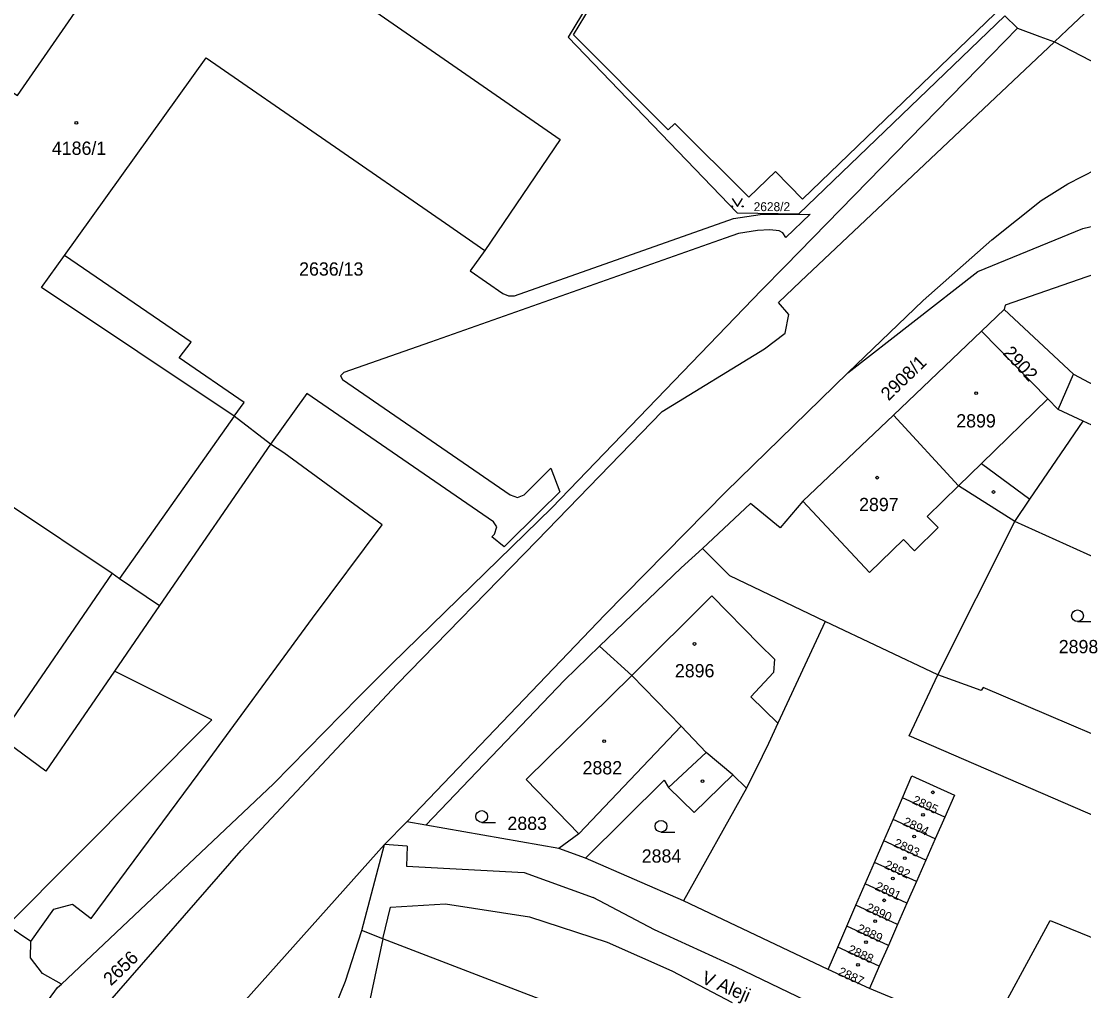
# Model space of a CAD drawing. Extents: x -527335 to -526256, y -1079142 to -1077836.
# Drawn here: x -527027.3 to -526891.4, y -1078723.7 to -1078599.7 of the extents above; entities that cross this region are included whole.
import ezdxf

# ---------------------------------------------------------------- set-up
doc = ezdxf.new("R2010")
doc.units = 0
for name, color, linetype in [('Hranice parcel', 7, 'Continuous'), ('Parcelní čísla', 7, 'Continuous'), ('Pop  PČ popisy', 7, 'Continuous'), ('Vnitřní kresba', 7, 'Continuous'), ('Značky budov', 7, 'Continuous'), ('Značky kultur', 7, 'Continuous')]:
    doc.layers.add(name, color=color, linetype=linetype)

msp = doc.modelspace()

# ---------------------------------------------------------------- linework, layer by layer
at = {"layer": 'Hranice parcel'}
for p, q in [((-526895.17, -1078602.34), (-526879.54, -1078610.46)), ((-526901.58, -1078636.57), (-526904.48, -1078639.35)), ((-526892.72, -1078644.86), (-526901.58, -1078636.57)), ((-526904.48, -1078639.35), (-526915.77, -1078650.08)), ((-526894.69, -1078649.36), (-526892.72, -1078644.86)), ((-527000.1, -1078650.22), (-527014.76, -1078670.99)), ((-526891.48, -1078650.84), (-526894.69, -1078649.36)), ((-526910.1, -1078683.31), (-526900.22, -1078663.69)), ((-526884.81, -1078670.65), (-526900.22, -1078663.69)), ((-526910.1, -1078683.31), (-526924.49, -1078676.46)), ((-526949.23, -1078683.38), (-526953.38, -1078679.65)), ((-526934.57, -1078697.78), (-526936.31, -1078696.09)), ((-526934.57, -1078697.78), (-526942.6, -1078712.19)), ((-526915.81, -1078701.79), (-526914.61, -1078699.02)), ((-526909.18, -1078701.49), (-526914.61, -1078699.02)), ((-526916.99, -1078704.52), (-526915.81, -1078701.79)), ((-526910.4, -1078704.26), (-526915.81, -1078701.79)), ((-526909.18, -1078701.49), (-526910.4, -1078704.26)), ((-526978.03, -1078702.08), (-526980.85, -1078705.02)), ((-526975.57, -1078702.51), (-526978.03, -1078702.08)), ((-526958.56, -1078705.51), (-526975.57, -1078702.51)), ((-526918.19, -1078707.29), (-526916.99, -1078704.52)), ((-526911.6, -1078706.99), (-526916.99, -1078704.52)), ((-526910.4, -1078704.26), (-526911.6, -1078706.99)), ((-526980.85, -1078705.02), (-526998.63, -1078724.92)), ((-526955.16, -1078706.76), (-526958.56, -1078705.51)), ((-526942.6, -1078712.19), (-526955.16, -1078706.76)), ((-526919.38, -1078710.05), (-526918.19, -1078707.29)), ((-526912.82, -1078709.75), (-526918.19, -1078707.29)), ((-526911.6, -1078706.99), (-526912.82, -1078709.75)), ((-526920.56, -1078712.77), (-526919.38, -1078710.05)), ((-526914.03, -1078712.51), (-526919.38, -1078710.05)), ((-526912.82, -1078709.75), (-526914.03, -1078712.51)), ((-526924.11, -1078720.97), (-526942.6, -1078712.19)), ((-526921.72, -1078715.45), (-526920.56, -1078712.77)), ((-526915.22, -1078715.23), (-526920.56, -1078712.77)), ((-526914.03, -1078712.51), (-526915.22, -1078715.23)), ((-526922.88, -1078718.12), (-526921.72, -1078715.45)), ((-526916.4, -1078717.9), (-526921.72, -1078715.45)), ((-526915.22, -1078715.23), (-526916.4, -1078717.9)), ((-526924.11, -1078720.97), (-526922.88, -1078718.12)), ((-526917.58, -1078720.58), (-526922.88, -1078718.12)), ((-526916.4, -1078717.9), (-526917.58, -1078720.58)), ((-526918.83, -1078723.42), (-526924.11, -1078720.97)), ((-526917.58, -1078720.58), (-526918.83, -1078723.42))]:
    msp.add_line(p, q, dxfattribs=at)
for points in [[(-527032.9, -1078614.69), (-527028.96, -1078608.95), (-527028.74, -1078608.62), (-527027.84, -1078609.21), (-527013.93, -1078589.06), (-527018.97, -1078585.47), (-527022.71, -1078582.8), (-527034.32, -1078599.25), (-527035, -1078600.21), (-527045.31, -1078592.89), (-527044.64, -1078591.95), (-527045.34, -1078591.68), (-527030.72, -1078570.54), (-527019.5, -1078578.37), (-527020.66, -1078580.03), (-527011.71, -1078586.28), (-527007.77, -1078580.59), (-526958.39, -1078614.81), (-526968.02, -1078629.02)], [(-526886.71, -1078584.76), (-526887.47, -1078583.94), (-526927.4, -1078622.44), (-526930.86, -1078618.91), (-526934.27, -1078622.19), (-526943.73, -1078612.76), (-526944.56, -1078613.6), (-526956.67, -1078601.43), (-526954.52, -1078597.86), (-526954.82, -1078597.51)], [(-526895.17, -1078602.34), (-526893.54, -1078600.8), (-526885.48, -1078593.16)], [(-526954.82, -1078597.51), (-526957.37, -1078601.73), (-526935.75, -1078624.2), (-526927.86, -1078624.35), (-526901.5, -1078599), (-526901.11, -1078599.39)], [(-526901.11, -1078599.39), (-526900.32, -1078600.17), (-526899.88, -1078600.6)], [(-527022.2, -1078722.85), (-526995.09, -1078697.22), (-526984.19, -1078686.17), (-526979.99, -1078681.95), (-526959.44, -1078661.92), (-526932.63, -1078634.11), (-526929.59, -1078631.02), (-526904.86, -1078605.7), (-526899.88, -1078600.6)], [(-526899.88, -1078600.6), (-526897.02, -1078601.66), (-526895.17, -1078602.34)], [(-527072.22, -1078805.43), (-527063.35, -1078791.03), (-527051.39, -1078772.86), (-527021.8, -1078732.24), (-527016.31, -1078725.38), (-526999.22, -1078705.77), (-526979.26, -1078684.5), (-526961.36, -1078666.17), (-526945.34, -1078649.61), (-526932.24, -1078641.62), (-526929.63, -1078639.61), (-526929.14, -1078637.23), (-526930.46, -1078635.68), (-526927.65, -1078633), (-526895.17, -1078602.34)], [(-527000.1, -1078650.22), (-527024.76, -1078633.76), (-527021.82, -1078629.67), (-527003.67, -1078604.4), (-526973.08, -1078625.53), (-526968.02, -1078629.02)], [(-526921.59, -1078644.68), (-526911.97, -1078635.42), (-526903.16, -1078627.64), (-526896.85, -1078622.64), (-526893.43, -1078620.48), (-526889.76, -1078618.63), (-526885.07, -1078616.68), (-526879.09, -1078614.67), (-526871.32, -1078612.59), (-526869.37, -1078612.14)], [(-526921.59, -1078644.68), (-526904.95, -1078631.71), (-526891.51, -1078626.22), (-526880.24, -1078623.51), (-526871.73, -1078622.35), (-526857.21, -1078622.49), (-526853.17, -1078623.18)], [(-526968.02, -1078629.02), (-526969.91, -1078631.61), (-526965.71, -1078634.53), (-526965, -1078634.84), (-526964.22, -1078634.81), (-526936.22, -1078624.93), (-526932.79, -1078624.4), (-526926.41, -1078624.36), (-526929.51, -1078627.35), (-526929.91, -1078626.76), (-526930.39, -1078626.49), (-526931.57, -1078626.38), (-526933.16, -1078626.45), (-526935.56, -1078626.83), (-526937.3, -1078627.43), (-526974.99, -1078640.74), (-526986.08, -1078644.63), (-526986.49, -1078645.05), (-526986.23, -1078645.53), (-526964.78, -1078660.29), (-526963.85, -1078660.61), (-526963.02, -1078660.27), (-526959.57, -1078656.88), (-526958.42, -1078659.89), (-526960.97, -1078662.37), (-526965.58, -1078666.91), (-526967.12, -1078665.64), (-526966.8, -1078665.3), (-526966.51, -1078664.38), (-526966.91, -1078663.73), (-526990.82, -1078647.32), (-526995.44, -1078653.79), (-527000.1, -1078650.22)], [(-526878.81, -1078628.66), (-526882.67, -1078629.51), (-526901.46, -1078636.01), (-526901.58, -1078636.57)], [(-526894.69, -1078649.36), (-526896.02, -1078648), (-526904.48, -1078639.35)], [(-526978.03, -1078702.08), (-526952.67, -1078675.63), (-526937.2, -1078659.88), (-526921.59, -1078644.68)], [(-526892.72, -1078644.86), (-526888.78, -1078646.91), (-526881.81, -1078650.35)], [(-526915.77, -1078650.08), (-526927.35, -1078661.1), (-526930.24, -1078664.51), (-526934.06, -1078661.4), (-526940.18, -1078667.13)], [(-526900.22, -1078663.69), (-526907.42, -1078659.13), (-526915.77, -1078650.08)], [(-526900.22, -1078663.69), (-526898.33, -1078660.82), (-526891.48, -1078650.84)], [(-526884.81, -1078670.65), (-526875.97, -1078658.01), (-526891.48, -1078650.84)], [(-527028.7, -1078661.6), (-527015.73, -1078670.3), (-527014.76, -1078670.99)], [(-526940.18, -1078667.13), (-526942.9, -1078669.62), (-526953.38, -1078679.65)], [(-526924.49, -1078676.46), (-526936.71, -1078670.65), (-526940.18, -1078667.13)], [(-527014.76, -1078670.99), (-527009.64, -1078674.44), (-527015.39, -1078682.81)], [(-526924.49, -1078676.46), (-526930.54, -1078689.49), (-526931.74, -1078692.06), (-526932.57, -1078693.74), (-526934.57, -1078697.78)], [(-526953.38, -1078679.65), (-526957.82, -1078683.96), (-526975.57, -1078702.51)], [(-527015.39, -1078682.81), (-527024.2, -1078695.62), (-527030.14, -1078691.25), (-527037.08, -1078701.34), (-527042.08, -1078697.91)], [(-527022.2, -1078722.85), (-527024.62, -1078721.48), (-527026.17, -1078719.51), (-527026.1, -1078717.42), (-527029.13, -1078715.35), (-527002.95, -1078689.07), (-527015.39, -1078682.81)], [(-526949.23, -1078683.38), (-526962.73, -1078696.68), (-526956.02, -1078703.63), (-526958.56, -1078705.51)], [(-526936.31, -1078696.09), (-526939.72, -1078693.23), (-526942.93, -1078689.86), (-526949.23, -1078683.38)], [(-526887.47, -1078692.06), (-526904.29, -1078684.93), (-526904.54, -1078685.32), (-526910.1, -1078683.31)], [(-526955.16, -1078706.76), (-526945.11, -1078696.79), (-526944.54, -1078697.69), (-526941.25, -1078700.91), (-526936.31, -1078696.09)], [(-526914.61, -1078699.02), (-526913.4, -1078696.22), (-526907.94, -1078698.67), (-526909.18, -1078701.49)], [(-526943.47, -1078731.53), (-526981.07, -1078717.06), (-526983.77, -1078716), (-526980.85, -1078705.02)], [(-526903.84, -1078729.73), (-526895.72, -1078714.74), (-526874.21, -1078723.48)], [(-527026.84, -1078728.96), (-527025.8, -1078727.55), (-527022.69, -1078723.31), (-527022.2, -1078722.85)], [(-526903.84, -1078729.73), (-526908.52, -1078727.66), (-526909.18, -1078727.41), (-526918.83, -1078723.42)]]:
    msp.add_lwpolyline(points, dxfattribs=at)
at = {"layer": 'Vnitřní kresba'}
for p, q in [((-527005.61, -1078640.76), (-527021.82, -1078629.67)), ((-527007.15, -1078642.76), (-527005.61, -1078640.76)), ((-526998.84, -1078648.48), (-527007.15, -1078642.76)), ((-527000.1, -1078650.22), (-526998.84, -1078648.48)), ((-526904.5, -1078656.28), (-526896.02, -1078648)), ((-526995.44, -1078653.79), (-527009.64, -1078674.44)), ((-526993.74, -1078654.92), (-526995.44, -1078653.79)), ((-526981.15, -1078664.11), (-526993.74, -1078654.92)), ((-526907.42, -1078659.13), (-526904.5, -1078656.28)), ((-526904.5, -1078656.28), (-526898.33, -1078660.82)), ((-526911.43, -1078663.04), (-526907.42, -1078659.13)), ((-526927.35, -1078661.1), (-526918.8, -1078670.23)), ((-526910.03, -1078664.47), (-526911.43, -1078663.04)), ((-526990.1, -1078676.05), (-526981.15, -1078664.11)), ((-526913.07, -1078667.44), (-526910.03, -1078664.47)), ((-526918.8, -1078670.23), (-526914.47, -1078666)), ((-526914.47, -1078666), (-526913.07, -1078667.44)), ((-527015.73, -1078670.3), (-527030.14, -1078691.25)), ((-526949.23, -1078683.38), (-526939, -1078673.18)), ((-526939, -1078673.18), (-526932.89, -1078679.41)), ((-527004.71, -1078696.01), (-526990.1, -1078676.05)), ((-526932.89, -1078679.41), (-526930.97, -1078681.31)), ((-526930.97, -1078681.31), (-526931.09, -1078683.01)), ((-526931.09, -1078683.01), (-526934, -1078686.1)), ((-526913.74, -1078691.1), (-526910.1, -1078683.31)), ((-526934, -1078686.1), (-526930.54, -1078689.49)), ((-526956.02, -1078703.63), (-526942.93, -1078689.86)), ((-526884.03, -1078703.98), (-526913.74, -1078691.1)), ((-526944.54, -1078697.69), (-526939.72, -1078693.23)), ((-527018.38, -1078714.47), (-527004.71, -1078696.01)), ((-526977.98, -1078705.21), (-526980.85, -1078705.02)), ((-526977.98, -1078705.21), (-526978.05, -1078707.78)), ((-526978.05, -1078707.78), (-526962.99, -1078708.6)), ((-526962.99, -1078708.6), (-526954.18, -1078711.78)), ((-527023.18, -1078713.29), (-527020.8, -1078712.65)), ((-527020.8, -1078712.65), (-527018.38, -1078714.47)), ((-526980.09, -1078713), (-526973.08, -1078712.58)), ((-526973.08, -1078712.58), (-526962.3, -1078714.24)), ((-526946.33, -1078715.93), (-526954.18, -1078711.78)), ((-527026.1, -1078717.42), (-527023.18, -1078713.29)), ((-526981.07, -1078717.06), (-526980.09, -1078713)), ((-526962.3, -1078714.24), (-526952.38, -1078717.51)), ((-526985.84, -1078722.46), (-526983.77, -1078716)), ((-526935.89, -1078720.7), (-526946.33, -1078715.93)), ((-526981.07, -1078717.06), (-526982.85, -1078725.3)), ((-526952.38, -1078717.51), (-526944.09, -1078721.15)), ((-526925.87, -1078725.49), (-526935.89, -1078720.7)), ((-526944.09, -1078721.15), (-526936.39, -1078725.2)), ((-526987.91, -1078727.56), (-526985.84, -1078722.46))]:
    msp.add_line(p, q, dxfattribs=at)
at = {"layer": 'Značky budov'}
for centre in [(-527020.29, -1078612.68), (-526905.16, -1078647.26), (-526917.84, -1078658.08), (-526902.95, -1078659.91), (-526941.22, -1078679.35), (-526952.78, -1078691.78), (-526940.18, -1078696.91), (-526910.73, -1078698.33), (-526911.98, -1078701.22), (-526913.09, -1078703.99), (-526914.3, -1078706.75), (-526915.82, -1078709.35), (-526916.95, -1078712.14), (-526918.11, -1078714.82), (-526919.27, -1078717.49), (-526920.29, -1078720.4)]:
    msp.add_circle(centre, 0.175, dxfattribs=at)
at = {"layer": 'Značky kultur'}
for p, q in [((-526892.21, -1078676.49), (-526890.46, -1078676.49)), ((-526968.43, -1078702.17), (-526966.68, -1078702.17)), ((-526945.49, -1078703.41), (-526943.74, -1078703.41))]:
    msp.add_line(p, q, dxfattribs=at)
msp.add_lwpolyline([(-526936.39, -1078622.38), (-526935.72, -1078623.39), (-526935.05, -1078622.38)], dxfattribs=at)
for centre, radius in [((-526936.39, -1078623.39), 0.067), ((-526935.05, -1078623.39), 0.067), ((-526892.21, -1078675.74), 0.75), ((-526968.43, -1078701.42), 0.75), ((-526945.49, -1078702.66), 0.75)]:
    msp.add_circle(centre, radius, dxfattribs=at)

# ---------------------------------------------------------------- texts
at = {"layer": 'Parcelní čísla'}
for s, height, p in [('4186/1', 1.7, (-527023.42, -1078616.79)), ('2628/2', 1.14, (-526933.64, -1078623.99)), ('2636/13', 1.7, (-526991.79, -1078632.24)), ('2899', 1.7, (-526907.72, -1078651.66)), ('2897', 1.7, (-526920.15, -1078662.36)), ('2898', 1.7, (-526894.61, -1078680.54)), ('2896', 1.7, (-526943.72, -1078683.62)), ('2882', 1.7, (-526955.53, -1078696.03)), ('2883', 1.7, (-526965.14, -1078703.14)), ('2884', 1.7, (-526947.96, -1078707.32))]:
    msp.add_text(s, height=height, dxfattribs=at).set_placement(p)
for s, height, rotation, p in [('2902', 1.7, 313, (-526901.84, -1078642.2)), ('2908/1', 1.7, 44, (-526916.38, -1078648.33)), ('2895', 1.14, 335, (-526913.44, -1078699.7)), ('2894', 1.14, 335, (-526914.64, -1078702.47)), ('2893', 1.14, 335, (-526915.82, -1078705.2)), ('2892', 1.14, 335, (-526917.02, -1078707.97)), ('2891', 1.14, 335, (-526918.21, -1078710.73)), ('2890', 1.14, 335, (-526919.39, -1078713.45)), ('2889', 1.14, 335, (-526920.55, -1078716.13)), ('2888', 1.14, 335, (-526921.71, -1078718.8)), ('2656', 1.7, 44, (-527015.86, -1078723.17)), ('2887', 1.14, 335, (-526922.94, -1078721.65))]:
    msp.add_text(s, height=height, rotation=rotation, dxfattribs=at).set_placement(p)
at = {"layer": 'Pop  PČ popisy'}
msp.add_text('V Aleji', height=1.7, rotation=337, dxfattribs=at).set_placement((-526940.44, -1078722.67))

doc.saveas('drawing.dxf')
